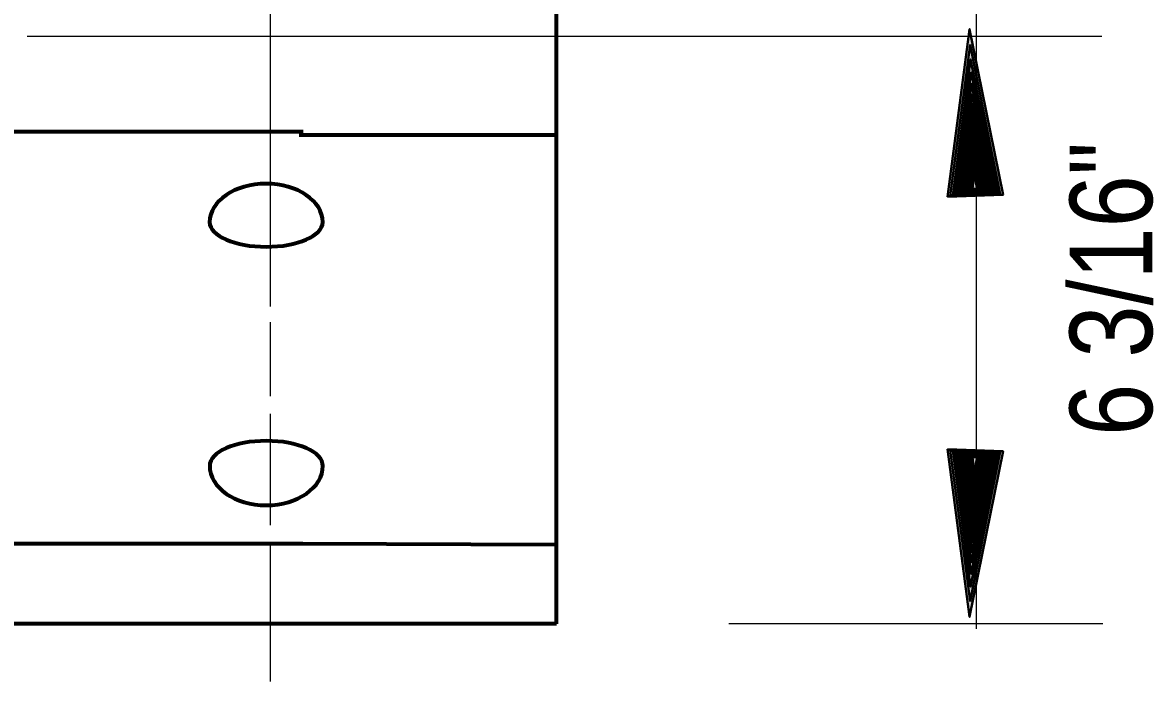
# Model space of a CAD drawing. Extents: x 895.6 to 930.4, y -2278.6 to -2254.7.
# Drawn here: x 918.313 to 920.074, y -2273.927 to -2272.9 of the extents above; entities that cross this region are included whole.
import ezdxf

# ---------------------------------------------------------------- set-up
doc = ezdxf.new("R2010")
doc.units = 0
doc.header["$LTSCALE"] = 0.051
doc.layers.add('1', color=7, linetype='Continuous', lineweight=70)
doc.layers.add('3', color=7, linetype='Continuous', lineweight=40)

msp = doc.modelspace()

# ---------------------------------------------------------------- hatches: boundary and pattern name
at = {"layer": '3'}
for points in [[(919.75367, -2273.17117), (919.84033, -2273.16825), (919.78817, -2272.90983), (919.78817, -2272.90983)], [(919.758, -2273.16992), (919.836, -2273.16717), (919.789, -2272.93458), (919.789, -2272.93458)], [(919.76192, -2273.16867), (919.832, -2273.16633), (919.78975, -2272.957), (919.78975, -2272.957)], [(919.76533, -2273.16767), (919.82842, -2273.1655), (919.79042, -2272.977), (919.79042, -2272.977)], [(919.76833, -2273.16675), (919.82517, -2273.16483), (919.791, -2272.99508), (919.791, -2272.99508)], [(919.77125, -2273.16567), (919.82233, -2273.16408), (919.7915, -2273.01133), (919.7915, -2273.01133)], [(919.77383, -2273.165), (919.81975, -2273.1635), (919.792, -2273.02608), (919.792, -2273.02608)], [(919.776, -2273.16417), (919.8175, -2273.16292), (919.7925, -2273.03933), (919.7925, -2273.03933)], [(919.778, -2273.16375), (919.81542, -2273.16242), (919.793, -2273.05108), (919.793, -2273.05108)], [(919.78, -2273.163), (919.81367, -2273.16183), (919.79333, -2273.06192), (919.79333, -2273.06192)], [(919.7815, -2273.16258), (919.81183, -2273.1615), (919.79358, -2273.0715), (919.79358, -2273.0715)], [(919.78308, -2273.16208), (919.81025, -2273.16108), (919.794, -2273.08008), (919.794, -2273.08008)], [(919.78442, -2273.16167), (919.80892, -2273.16083), (919.79425, -2273.088), (919.79425, -2273.088)], [(919.78567, -2273.16108), (919.80775, -2273.16058), (919.79442, -2273.09492), (919.79442, -2273.09492)], [(919.78675, -2273.16092), (919.80658, -2273.16025), (919.79458, -2273.10117), (919.79458, -2273.10117)], [(919.78775, -2273.1605), (919.80558, -2273.16008), (919.79492, -2273.10683), (919.79492, -2273.10683)], [(919.78867, -2273.16033), (919.80475, -2273.15975), (919.79508, -2273.11192), (919.79508, -2273.11192)], [(919.7895, -2273.16017), (919.80392, -2273.15958), (919.79525, -2273.1165), (919.79525, -2273.1165)], [(919.78992, -2273.15975), (919.80308, -2273.1595), (919.79525, -2273.12058), (919.79525, -2273.12058)], [(919.7905, -2273.15958), (919.80233, -2273.15917), (919.79533, -2273.12425), (919.79533, -2273.12425)], [(919.791, -2273.15925), (919.80158, -2273.15883), (919.79517, -2273.1275), (919.79517, -2273.1275)], [(919.79158, -2273.15925), (919.801, -2273.15883), (919.79533, -2273.13058), (919.79533, -2273.13058)], [(919.79208, -2273.15908), (919.80058, -2273.15875), (919.79558, -2273.13333), (919.79558, -2273.13333)], [(919.7925, -2273.15883), (919.80008, -2273.15867), (919.7955, -2273.13567), (919.7955, -2273.13567)], [(919.75367, -2273.565), (919.84033, -2273.56792), (919.78817, -2273.82633), (919.78817, -2273.82633)], [(919.758, -2273.56625), (919.836, -2273.569), (919.789, -2273.80158), (919.789, -2273.80158)], [(919.76192, -2273.5675), (919.832, -2273.56983), (919.78975, -2273.77917), (919.78975, -2273.77917)], [(919.76533, -2273.5685), (919.82842, -2273.57067), (919.79042, -2273.75917), (919.79042, -2273.75917)], [(919.76833, -2273.56942), (919.82517, -2273.57133), (919.791, -2273.74108), (919.791, -2273.74108)], [(919.77125, -2273.5705), (919.82233, -2273.57208), (919.7915, -2273.72483), (919.7915, -2273.72483)], [(919.77383, -2273.57117), (919.81975, -2273.57267), (919.792, -2273.71008), (919.792, -2273.71008)], [(919.776, -2273.572), (919.8175, -2273.57325), (919.7925, -2273.69683), (919.7925, -2273.69683)], [(919.778, -2273.57242), (919.81542, -2273.57375), (919.793, -2273.68508), (919.793, -2273.68508)], [(919.78, -2273.57317), (919.81367, -2273.57433), (919.79333, -2273.67425), (919.79333, -2273.67425)], [(919.7815, -2273.57358), (919.81183, -2273.57467), (919.79358, -2273.66467), (919.79358, -2273.66467)], [(919.78308, -2273.57408), (919.81025, -2273.57508), (919.794, -2273.65608), (919.794, -2273.65608)], [(919.78442, -2273.5745), (919.80892, -2273.57533), (919.79425, -2273.64817), (919.79425, -2273.64817)], [(919.78567, -2273.57508), (919.80775, -2273.57558), (919.79442, -2273.64125), (919.79442, -2273.64125)], [(919.78675, -2273.57525), (919.80658, -2273.57592), (919.79458, -2273.635), (919.79458, -2273.635)], [(919.78775, -2273.57567), (919.80558, -2273.57608), (919.79492, -2273.62933), (919.79492, -2273.62933)], [(919.78867, -2273.57583), (919.80475, -2273.57642), (919.79508, -2273.62425), (919.79508, -2273.62425)], [(919.7895, -2273.576), (919.80392, -2273.57658), (919.79525, -2273.61967), (919.79525, -2273.61967)], [(919.78992, -2273.57642), (919.80308, -2273.57667), (919.79525, -2273.61558), (919.79525, -2273.61558)], [(919.7905, -2273.57658), (919.80233, -2273.577), (919.79533, -2273.61192), (919.79533, -2273.61192)], [(919.791, -2273.57692), (919.80158, -2273.57733), (919.79517, -2273.60867), (919.79517, -2273.60867)], [(919.79158, -2273.57692), (919.801, -2273.57733), (919.79533, -2273.60558), (919.79533, -2273.60558)], [(919.79208, -2273.57708), (919.80058, -2273.57742), (919.79558, -2273.60283), (919.79558, -2273.60283)], [(919.7925, -2273.57733), (919.80008, -2273.5775), (919.7955, -2273.6005), (919.7955, -2273.6005)]]:
    msp.add_hatch(color=256, dxfattribs=at).paths.add_polyline_path(points)

# ---------------------------------------------------------------- linework, layer by layer
at = {"layer": '1', "lineweight": 25}
for p, q in [((918.69942, -2273.34217), (918.69942, -2270.69617)), ((919.79892, -2273.84467), (919.79892, -2271.02042)), ((918.32025, -2272.92083), (919.99442, -2272.92083)), ((918.69942, -2273.48225), (918.69942, -2273.3665)), ((918.69942, -2273.68325), (918.69942, -2273.50967)), ((918.69942, -2273.92683), (918.69942, -2273.71058)), ((919.413, -2273.83642), (919.99592, -2273.83642))]:
    msp.add_line(p, q, dxfattribs=at)
at = {"layer": '1'}
for p, q in [((919.14467, -2273.83717), (919.14467, -2271.04083)), ((918.75017, -2273.06975), (917.25817, -2273.06975)), ((919.14617, -2273.07533), (918.74383, -2273.07533)), ((919.14467, -2273.83717), (915.53433, -2273.83717))]:
    msp.add_line(p, q, dxfattribs=at)
msp.add_lwpolyline([(917.25717, -2273.71167), (918.74917, -2273.71167), (919.14208, -2273.71317)], dxfattribs=at)
for centre, major_axis, ratio in [((918.69251, -2273.21089), (-0.08819, 0), 0.679978), ((918.69251, -2273.21089), (0.08819, 0), 0.434256), ((918.69267, -2273.59087), (-0.08819, 0), 0.442883), ((918.69267, -2273.59087), (0.08819, 0), 0.696674)]:
    msp.add_ellipse(centre, major_axis=major_axis, ratio=ratio, start_param=3.1415927, end_param=6.2831853, dxfattribs=at)
at = {"layer": '3'}
for points in [[(919.75367, -2273.17117), (919.84033, -2273.16825), (919.78817, -2272.90983), (919.78817, -2272.90983)], [(919.758, -2273.16992), (919.836, -2273.16717), (919.789, -2272.93458), (919.789, -2272.93458)], [(919.76192, -2273.16867), (919.832, -2273.16633), (919.78975, -2272.957), (919.78975, -2272.957)], [(919.76533, -2273.16767), (919.82842, -2273.1655), (919.79042, -2272.977), (919.79042, -2272.977)], [(919.76833, -2273.16675), (919.82517, -2273.16483), (919.791, -2272.99508), (919.791, -2272.99508)], [(919.77125, -2273.16567), (919.82233, -2273.16408), (919.7915, -2273.01133), (919.7915, -2273.01133)], [(919.77383, -2273.165), (919.81975, -2273.1635), (919.792, -2273.02608), (919.792, -2273.02608)], [(919.776, -2273.16417), (919.8175, -2273.16292), (919.7925, -2273.03933), (919.7925, -2273.03933)], [(919.778, -2273.16375), (919.81542, -2273.16242), (919.793, -2273.05108), (919.793, -2273.05108)], [(919.78, -2273.163), (919.81367, -2273.16183), (919.79333, -2273.06192), (919.79333, -2273.06192)], [(919.7815, -2273.16258), (919.81183, -2273.1615), (919.79358, -2273.0715), (919.79358, -2273.0715)], [(919.78308, -2273.16208), (919.81025, -2273.16108), (919.794, -2273.08008), (919.794, -2273.08008)], [(919.78442, -2273.16167), (919.80892, -2273.16083), (919.79425, -2273.088), (919.79425, -2273.088)], [(919.78567, -2273.16108), (919.80775, -2273.16058), (919.79442, -2273.09492), (919.79442, -2273.09492)], [(919.78675, -2273.16092), (919.80658, -2273.16025), (919.79458, -2273.10117), (919.79458, -2273.10117)], [(919.78775, -2273.1605), (919.80558, -2273.16008), (919.79492, -2273.10683), (919.79492, -2273.10683)], [(919.78867, -2273.16033), (919.80475, -2273.15975), (919.79508, -2273.11192), (919.79508, -2273.11192)], [(919.7895, -2273.16017), (919.80392, -2273.15958), (919.79525, -2273.1165), (919.79525, -2273.1165)], [(919.78992, -2273.15975), (919.80308, -2273.1595), (919.79525, -2273.12058), (919.79525, -2273.12058)], [(919.7905, -2273.15958), (919.80233, -2273.15917), (919.79533, -2273.12425), (919.79533, -2273.12425)], [(919.791, -2273.15925), (919.80158, -2273.15883), (919.79517, -2273.1275), (919.79517, -2273.1275)], [(919.79158, -2273.15925), (919.801, -2273.15883), (919.79533, -2273.13058), (919.79533, -2273.13058)], [(919.79208, -2273.15908), (919.80058, -2273.15875), (919.79558, -2273.13333), (919.79558, -2273.13333)], [(919.7925, -2273.15883), (919.80008, -2273.15867), (919.7955, -2273.13567), (919.7955, -2273.13567)], [(919.75367, -2273.565), (919.84033, -2273.56792), (919.78817, -2273.82633), (919.78817, -2273.82633)], [(919.758, -2273.56625), (919.836, -2273.569), (919.789, -2273.80158), (919.789, -2273.80158)], [(919.76192, -2273.5675), (919.832, -2273.56983), (919.78975, -2273.77917), (919.78975, -2273.77917)], [(919.76533, -2273.5685), (919.82842, -2273.57067), (919.79042, -2273.75917), (919.79042, -2273.75917)], [(919.76833, -2273.56942), (919.82517, -2273.57133), (919.791, -2273.74108), (919.791, -2273.74108)], [(919.77125, -2273.5705), (919.82233, -2273.57208), (919.7915, -2273.72483), (919.7915, -2273.72483)], [(919.77383, -2273.57117), (919.81975, -2273.57267), (919.792, -2273.71008), (919.792, -2273.71008)], [(919.776, -2273.572), (919.8175, -2273.57325), (919.7925, -2273.69683), (919.7925, -2273.69683)], [(919.778, -2273.57242), (919.81542, -2273.57375), (919.793, -2273.68508), (919.793, -2273.68508)], [(919.78, -2273.57317), (919.81367, -2273.57433), (919.79333, -2273.67425), (919.79333, -2273.67425)], [(919.7815, -2273.57358), (919.81183, -2273.57467), (919.79358, -2273.66467), (919.79358, -2273.66467)], [(919.78308, -2273.57408), (919.81025, -2273.57508), (919.794, -2273.65608), (919.794, -2273.65608)], [(919.78442, -2273.5745), (919.80892, -2273.57533), (919.79425, -2273.64817), (919.79425, -2273.64817)], [(919.78567, -2273.57508), (919.80775, -2273.57558), (919.79442, -2273.64125), (919.79442, -2273.64125)], [(919.78675, -2273.57525), (919.80658, -2273.57592), (919.79458, -2273.635), (919.79458, -2273.635)], [(919.78775, -2273.57567), (919.80558, -2273.57608), (919.79492, -2273.62933), (919.79492, -2273.62933)], [(919.78867, -2273.57583), (919.80475, -2273.57642), (919.79508, -2273.62425), (919.79508, -2273.62425)], [(919.7895, -2273.576), (919.80392, -2273.57658), (919.79525, -2273.61967), (919.79525, -2273.61967)], [(919.78992, -2273.57642), (919.80308, -2273.57667), (919.79525, -2273.61558), (919.79525, -2273.61558)], [(919.7905, -2273.57658), (919.80233, -2273.577), (919.79533, -2273.61192), (919.79533, -2273.61192)], [(919.791, -2273.57692), (919.80158, -2273.57733), (919.79517, -2273.60867), (919.79517, -2273.60867)], [(919.79158, -2273.57692), (919.801, -2273.57733), (919.79533, -2273.60558), (919.79533, -2273.60558)], [(919.79208, -2273.57708), (919.80058, -2273.57742), (919.79558, -2273.60283), (919.79558, -2273.60283)], [(919.7925, -2273.57733), (919.80008, -2273.5775), (919.7955, -2273.6005), (919.7955, -2273.6005)]]:
    msp.add_lwpolyline(points, close=True, dxfattribs=at)

# ---------------------------------------------------------------- texts
at = {"layer": '1', "width": 0.85}
msp.add_text('6 3/16"', height=0.1286, rotation=90, dxfattribs=at).set_placement((920.07267, -2273.544))

doc.saveas('drawing.dxf')
